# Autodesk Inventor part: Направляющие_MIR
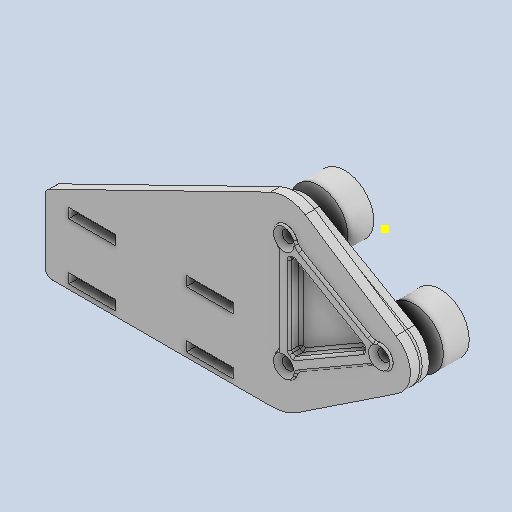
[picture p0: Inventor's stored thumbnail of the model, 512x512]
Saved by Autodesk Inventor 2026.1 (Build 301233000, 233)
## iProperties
Created: 2025-12
Part Number: Направляющие_MIR
Material: Типовые
Document SubType Name: Modeling
Designer: Yury Melnikov
Density: 1 g/cm^3
Appearance: По умолчанию
Author: Yury Melnikov
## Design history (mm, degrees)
derived "Направляющие.ipt"
  sketch "Эскиз1"
    geometry: L1 (0, 0)-(-16, 0) reference; L2 (-16, 0)-(-16, -200) reference; L3 (-16, -200)-(0, -200) reference; L4 (0, -200)-(0, 0) reference; 1 further point
  sketch "Эскиз2"
    geometry: 1 further point
  sketch "Эскиз3"
    geometry: L1 (0, 0)-(0, -200) reference; L2 (16, -200)-(16, 0) reference; L3 (28.3, -33.725)-(-12.3, -10.284) reference; L4 (-12.3, -10.284)-(-12.3, -57.165) reference; L5 (-12.3, -57.165)-(28.3, -33.725) reference; C1 r 12.3 at (28.3, -33.725) reference; C2 r 12.3 at (-12.3, -10.284) reference; C3 r 12.3 at (-12.3, -57.165) reference; 1 further point
    constraints: 1 other
  sketch "Эскиз4"
    geometry: C1 r 12.3 at (0, 0) reference; C2 r 12.3 at (-40.6, 23.44) reference; C3 r 12.3 at (-40.6, -23.44) reference; C4 r 4 at (0, 0) reference; C5 r 4 at (-40.6, 23.44) reference; C6 r 4 at (-40.6, -23.44) reference; 1 further point
  sketch "Эскиз5"
    geometry: L1 (6.15, 10.652)-(-34.45, 34.093) reference; L2 (-52.9, 23.44)-(-52.9, -23.44) reference; L3 (-34.45, -34.093)-(6.15, -10.652) reference; A1 r 12.3 centre (-40.6, -23.44) between (-34.45, -34.093) and (-52.9, -23.44) reference; A2 r 12.3 centre (-40.6, 23.44) between (-52.9, 23.44) and (-34.45, 34.093) reference; A3 r 12.3 centre (0, 0) between (6.15, -10.652) and (6.15, 10.652) reference; 1 further point
  sketch "Эскиз6"
    geometry: L1 (0, 0)-(-40.6, 23.44) reference; L2 (-40.6, 23.44)-(-40.6, -23.44) reference; L3 (-40.6, -23.44)-(0, 0) reference; L4 (-35.6, 23.44)-(-2.5, 4.33) reference; L5 (-2.5, -4.33)-(-35.6, -23.44) reference; L6 (-43.1, -19.11)-(-43.1, 19.11) reference; L7 (-38.1, 19.11)-(-5, 0) reference; L8 (-5, 0)-(-38.1, -19.11) reference; L9 (-38.1, -19.11)-(-38.1, 19.11) reference; C1 r 12.3 at (-40.6, 23.44) reference; C2 r 12.3 at (-40.6, -23.44) reference; C3 r 12.3 at (0, 0) reference; C4 r 2.5 at (0, 0) reference; C5 r 2.5 at (-40.6, 23.44) reference; C6 r 2.5 at (-40.6, -23.44) reference; A1 r 5 centre (-40.6, 23.44) between (-35.6, 23.44) and (-43.1, 19.11) reference; A2 r 5 centre (0, 0) between (-2.5, -4.33) and (-2.5, 4.33) reference; A3 r 5 centre (-40.6, -23.44) between (-43.1, -19.11) and (-35.6, -23.44) reference; 3 further points
    constraints: 2 other
  sketch "Эскиз7"
    geometry: C1 r 2.5 at (-40.6, 23.44) reference; C2 r 2.5 at (0, 0) reference; C3 r 2.5 at (-40.6, -23.44) reference; 1 further point
  sketch "Эскиз8"
    geometry: L1 (-4.478, 5.472)-(-33.622, 22.298) reference; L2 (-43.1, 16.826)-(-43.1, -16.826) reference; L3 (-33.622, -22.298)-(-4.478, -5.472) reference; L4 (-34.45, 34.093)-(6.15, 10.652) reference; L5 (6.15, -10.652)-(-34.45, -34.093) reference; L6 (-52.9, -23.44)-(-52.9, 23.44) reference; L7 (-30, -82.992)-(-34, -82.992) reference; L8 (-28.3, 33.725)-(-28.3, -166.275) reference; L9 (-142.9, -11.74)-(-142.9, -38.74) reference; L10 (-139.9, -41.74)-(-46.638, -41.74) reference; L11 (-35.571, -38.399)-(6.806, -10.245) reference; L12 (-34.45, 34.093)-(6.15, 10.652) reference; L13 (6.15, 10.652)-(-32.359, 35.974) reference; L14 (-141.217, -9.045)-(-47.187, 36.917) reference; A1 r 5 centre (-1.978, -9.802) between (-0.989, -4.901) and (-4.478, -5.472) reference; A2 r 5 centre (0, 0) between (-0.989, -4.901) and (-0.989, 4.901) reference; A3 r 5 centre (-1.978, 9.802) between (-4.478, 5.472) and (-0.989, 4.901) reference; A4 r 5 centre (-31.122, 26.628) between (-35.861, 25.034) and (-33.622, 22.298) reference; A5 r 5 centre (-40.6, 23.44) between (-35.861, 25.034) and (-44.35, 20.133) reference; A6 r 5 centre (-48.1, 16.826) between (-43.1, 16.826) and (-44.35, 20.133) reference; A7 r 5 centre (-48.1, -16.826) between (-44.35, -20.133) and (-43.1, -16.826) reference; A8 r 5 centre (-40.6, -23.44) between (-44.35, -20.133) and (-35.861, -25.034) reference; A9 r 5 centre (-31.122, -26.628) between (-33.622, -22.298) and (-35.861, -25.034) reference; A10 r 12.3 centre (-40.6, 23.44) between (-34.45, 34.093) and (-52.9, 23.44) reference; A11 r 12.3 centre (0, 0) between (6.15, -10.652) and (6.15, 10.652) reference; A12 r 12.3 centre (-40.6, -23.44) between (-52.9, -23.44) and (-34.45, -34.093) reference; A13 r 12.3 centre (0, 0) between (6.15, -10.652) and (6.15, 10.652) reference; A14 r 12.3 centre (-40.6, 23.44) between (-34.45, 34.093) and (-52.9, 23.44) reference; A15 r 20 centre (-46.638, -21.74) between (-46.638, -41.74) and (-35.571, -38.399) reference; A16 r 3 centre (-139.9, -11.74) between (-141.217, -9.045) and (-142.9, -11.74) reference; A17 r 3 centre (-139.9, -38.74) between (-142.9, -38.74) and (-139.9, -41.74) reference; A18 r 15 centre (-40.6, 23.44) between (-28.3, 14.855) and (-26.541, 18.21) reference; A19 r 15 centre (-40.6, 23.44) between (-32.359, 35.974) and (-47.187, 36.917) reference; 5 further points
  node "РабПлоскость1"
feature "Твердое тело1::Направляющие.ipt" dims "d0" = 10
feature "Твердое тело2::Направляющие.ipt" dims "d0" = 10
feature "Каретка::Направляющие.ipt" dims "d0" = 10
feature "Рука::Направляющие.ipt" dims "d0" = 10
tag "Элемент создания тегов1"
sketch "Эскиз11"
  geometry: L1 (6.806, -10.245)-(-35.571, -38.399) reference; L2 (-46.638, -41.74)-(-139.9, -41.74) reference; L3 (-142.9, -38.74)-(-142.9, -11.74) reference; L4 (-33.622, -22.298)-(-4.478, -5.472) reference; L5 (-4.478, 5.472)-(-33.622, 22.298) reference; L6 (-43.1, 16.826)-(-43.1, -16.826) reference; L7 (-31.268, -35.54)-(-142.9, -35.54) reference; L8 (-37.92, -39.74)-(-142.728, -39.74) reference; L9 (-62.92, -35.54)-(-82.92, -35.54) reference; L10 (-82.92, -35.54)-(-82.92, -39.74) reference; L11 (-82.92, -39.74)-(-62.92, -39.74) reference; L12 (-62.92, -39.74)-(-62.92, -35.54) reference; L13 (-112.9, -35.54)-(-132.9, -35.54) reference; L14 (-132.9, -35.54)-(-132.9, -39.74) reference; L15 (-132.9, -39.74)-(-112.9, -39.74) reference; L16 (-112.9, -39.74)-(-112.9, -35.54) reference; L17 (-32.359, 35.974)-(6.15, 10.652) reference; L18 (-141.217, -9.045)-(-47.187, 36.917) reference; A1 r 12.3 centre (0, 0) between (6.806, -10.245) and (6.15, 10.652) reference; A2 r 20 centre (-46.638, -21.74) between (-46.638, -41.74) and (-35.571, -38.399) reference; A3 r 3 centre (-139.9, -38.74) between (-142.9, -38.74) and (-139.9, -41.74) reference; A4 r 3 centre (-139.9, -11.74) between (-141.217, -9.045) and (-142.9, -11.74) reference; A5 r 5 centre (-1.978, -9.802) between (-0.989, -4.901) and (-4.478, -5.472) reference; A6 r 5 centre (0, 0) between (-0.989, -4.901) and (-0.989, 4.901) reference; A7 r 5 centre (-1.978, 9.802) between (-4.478, 5.472) and (-0.989, 4.901) reference; A8 r 5 centre (-31.122, 26.628) between (-35.861, 25.034) and (-33.622, 22.298) reference; A9 r 5 centre (-40.6, 23.44) between (-35.861, 25.034) and (-44.35, 20.133) reference; A10 r 5 centre (-48.1, 16.826) between (-43.1, 16.826) and (-44.35, 20.133) reference; A11 r 5 centre (-48.1, -16.826) between (-44.35, -20.133) and (-43.1, -16.826) reference; A12 r 5 centre (-40.6, -23.44) between (-44.35, -20.133) and (-35.861, -25.034) reference; A13 r 5 centre (-31.122, -26.628) between (-33.622, -22.298) and (-35.861, -25.034) reference; A14 r 15 centre (-40.6, 23.44) between (-32.359, 35.974) and (-47.187, 36.917) reference; 1 further point
node "Твердое тело1"
node "Твердое тело2"
node "Каретка"
node "Рука"
